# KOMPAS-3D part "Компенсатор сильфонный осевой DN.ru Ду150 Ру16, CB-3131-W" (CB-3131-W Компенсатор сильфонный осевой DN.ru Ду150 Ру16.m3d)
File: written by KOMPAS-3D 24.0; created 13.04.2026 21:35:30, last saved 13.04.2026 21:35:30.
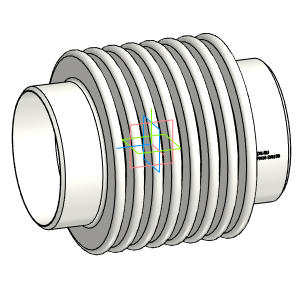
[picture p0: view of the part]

Document properties: Автор: DN.RU; Полное имя файла: D:\PROJECT CAD\DN.RU\...197(ACTUALE). CB-3131-W Компенсатор сильфонный осевой DN.ru\Исходники\DN150\CB-3131-W Компенсатор сильфонный осевой DN.ru Ду150 Ру16.m3d

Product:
- Body: Твердое тело1  | qty 1
    Масса: 8.265438
- Part/product: Компенсатор сильфонный осевой DN.ru Ду150 Ру16  | designation CB-3131-W
    Масса: 3.8
    Раздел спецификации: Прочие изделия
    Комментарий: D140-02126
    Примечание: D140-02126
    additional columns: Типовые

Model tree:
1. Твердое тело1  (labels: Твердое тело1)

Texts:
  CB-3131-W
